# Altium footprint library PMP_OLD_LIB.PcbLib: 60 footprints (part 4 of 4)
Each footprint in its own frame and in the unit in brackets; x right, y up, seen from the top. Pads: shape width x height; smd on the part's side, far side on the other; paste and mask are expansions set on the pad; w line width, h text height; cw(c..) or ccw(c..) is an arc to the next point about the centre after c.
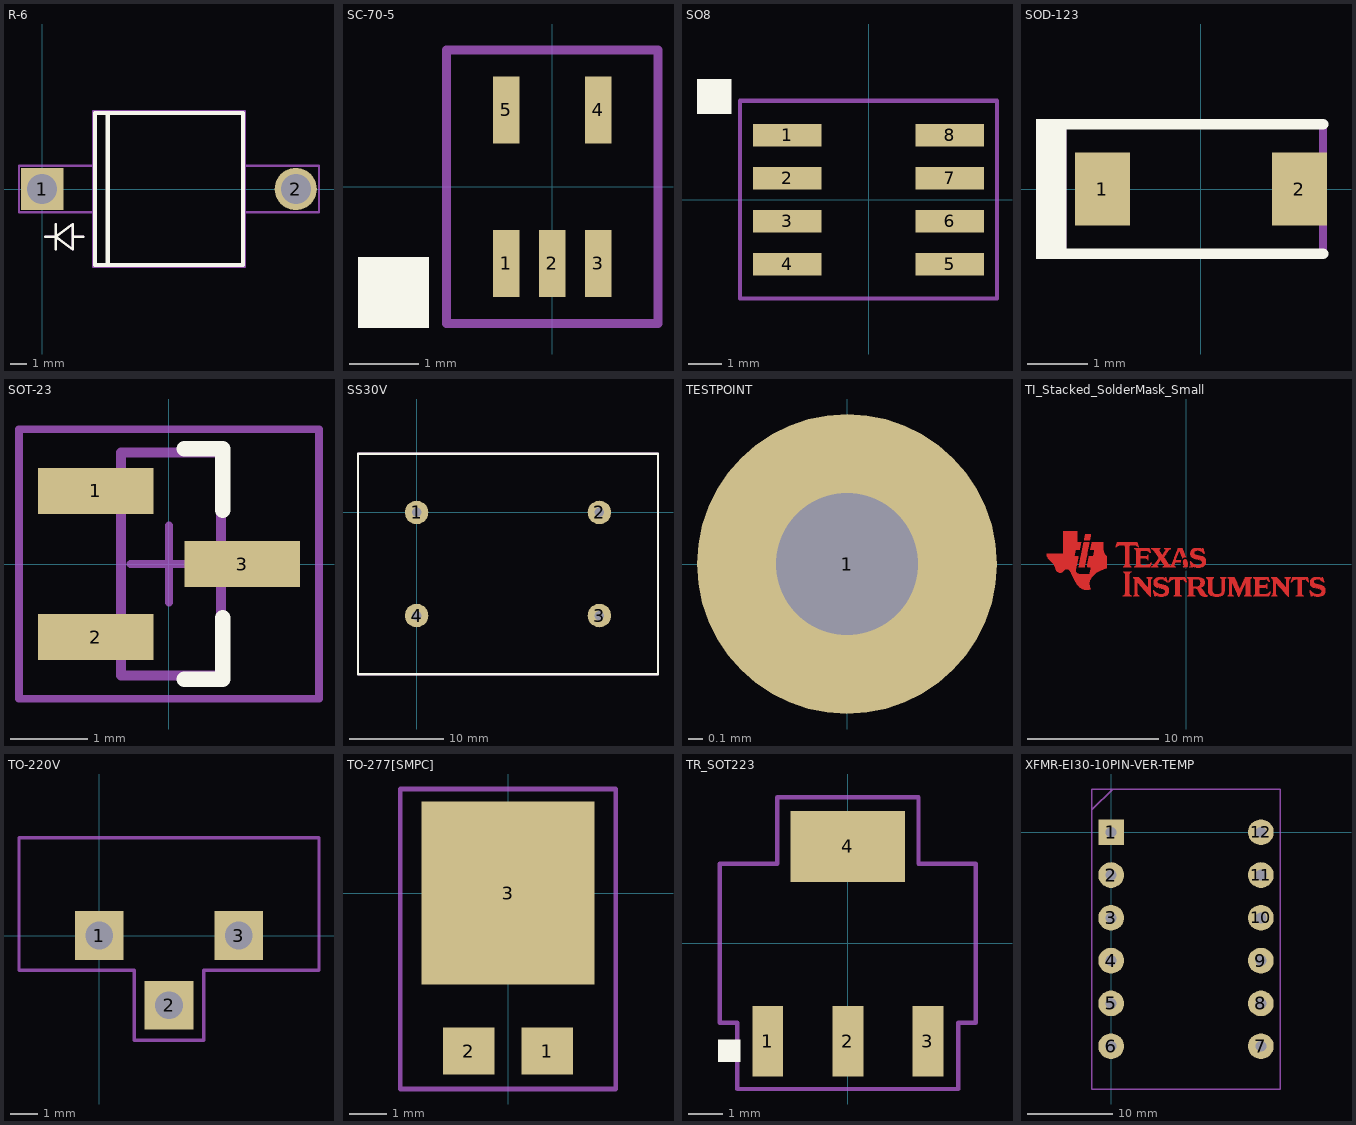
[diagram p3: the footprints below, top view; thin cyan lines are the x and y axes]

## R-6 [mil]
pads (2):
  rect 100x100 hole 71: 1(0,0)
  round 100 hole 71: 2(600,0)
Top Overlay:
  lines w6: 7.3,-113 32.3,-113 ; 32.3,-143 32.3,-83 ; 72.3,-113 97.3,-113 ; 32.3,-113 72.3,-143 72.3,-83 32.3,-113
  lines w10: 155,-180 155,180 ; 125,-180 475,-180 475,180 125,180 125,-180
Mechanical 5:
  lines w5: 7.3,-113 32.3,-113 ; 32.3,-143 32.3,-83 ; 72.3,-113 97.3,-113 ; 120,-55 -55,-55 -55,55 120,55 ; 480,-55 655,-55 655,55 480,55 ; 32.3,-113 72.3,-143 72.3,-83 32.3,-113 ; 120,-185 480,-185 480,185 120,185 120,-185
  text ".Designator" at 225,216.69 h60

## SC-70-5 [mil]
pads (5):
  rect 15x38 smd: 1(-25.9,-43.4) 2(0.1,-43.4) 3(26.1,-43.4) 4(26.1,43.6) 5(-25.9,43.6)
Top Overlay:
  region: -110,-80 -70,-80 -70,-40 -110,-40
Mechanical 5:
  lines w5: -59.9,-77.4 60.1,-77.4 60.1,77.6 -59.9,77.6 -59.9,-77.4
  text ".Designator" at -103,-12 h60
  text "*" at -50,-80 h25

## SO8 [mil]
pads (8):
  rect 80x26 smd: 1(-95,75) 2(-95,25) 3(-95,-25) 4(-95,-75) 5(94,-75) 6(94,-25) 7(94,25) 8(94,75)
Top Overlay:
  region: -160,100 -160,140 -200,140 -200,100
Mechanical 5:
  lines w5: -150,-115 149,-115 149,115 -150,115 -150,-115
  text ".Designator" at 40,155 h60

## SOD-123 [mm] "On Semi recommended land pattern"
height 1.35
pads (2):
  rect 0.915x1.22 smd: 1(-1.637,0) 2(1.637,0)
Top Overlay:
  rectangle: -2.743,-1.168 -2.235,1.168
  lines w0.178: -2.413,-1.079 2.032,-1.079 ; -2.413,1.079 2.032,1.079
Mechanical 5:
  rectangle: -2.743,-1.168 -2.235,1.168
  lines w0.127: -2.413,-1.079 2.032,-1.079 2.032,1.079 -2.413,1.079
  text ".Designator" at 1.143,2.819 h1.4
3D body: height 1.35, standoff 0, extent -1.932,-0.9 1.932,0.9

## SOT-23 [mm] "SOT23, 3-Leads, Body 2.9x1.3mm, Pitch 0.95mm, Lead Span 2.5mm, IPC Medium Density"
height 1.1
pads (3):
  rect 1.5x0.6 smd: 1(-0.95,0.95) 2(-0.95,-0.95) 3(0.95,0)
Top Overlay:
  lines w0.2: 0.2,-1.5 0.7,-1.5 0.7,-0.7 ; 0.2,1.5 0.7,1.5 0.7,0.7
Mechanical 5:
  lines w0.127: -1.16,-1.15 -1.16,-0.75 -0.625,-0.75 -0.625,0.75 -1.16,0.75 -1.16,1.15 -0.625,1.15 -0.625,1.45 0.675,1.45 0.675,0.2 1.21,0.2 1.21,-0.2 0.675,-0.2 0.675,-1.45 -0.625,-1.45 -0.625,-1.15 -1.16,-1.15
  text ".Designator" at -2.083,0.787 h1.52
Mechanical 15:
  lines w0.1: -0.5,0 0.5,0 ; 0,-0.5 0,0.5 ; -1.95,-1.75 1.95,-1.75 1.95,1.75 -1.95,1.75 -1.95,-1.75
3D body: height 1, standoff 0, extent -1.16,-1.45 1.21,1.45

## SS30V [mm]
pads (4):
  round 2.5 hole 1: 1(0,0) 2(19.5,0) 3(19.5,-11) 4(0,-11)
Top Overlay:
  lines w0.254: -6.25,-17.25 25.75,-17.25 25.75,6.25 -6.25,6.25 -6.25,-17.25
Mechanical 5:
  lines w0.254: -6.25,-17.25 -6.25,6.25 25.75,6.25 25.75,-17.25 -6.25,-17.25

## TESTPOINT [mil]
height 314.96
pads (1):
  round 80 hole 37.99: 1(0,0)

## TI_Stacked_SolderMask_Small [mil]
pads (1):
  rect 900x250 on Top Solder paste-125 mask-125: 0(0,0)
Top Layer:
  drawing of 18 lines, arcs and shapes, not listed

## TO-220V [mil]
pads (3):
  rect 70x70 hole 40: 1(0,0) 2(100,-100) 3(200,0)
Mechanical 5:
  lines w5: -115,-50 50,-50 50,-150 150,-150 150,-50 315,-50 315,140 -115,140 -115,-50
  text ".Designator" at -9.25,-88.9 h60

## TO-277[SMPC] [mil]
pads (3):
  rect 55x50 smd: 1(42,-168.6) 2(-42,-168.6)
  rect 185x195 smd: 3(0,0)
Mechanical 5:
  lines w5: -115,-209 115,-209 115,111 -115,111 -115,-209
  text ".Designator" at 165,-130 h60

## TR_SOT223 [mil]
pads (4):
  rect 35x80 smd: 1(-90.6,-110.9) 2(0,-110.9) 3(90.6,-110.9)
  rect 130x80 smd: 4(0,109.5)
Top Overlay:
  region: -146.8,-134.2 -146.8,-109.2 -121.8,-109.2 -121.8,-134.2
  region: -146.8,-134.2 -146.8,-109.2 -121.8,-109.2 -121.8,-134.2
Mechanical 5:
  lines w5: -145,-90 -125,-90 -125,-165 125,-165 125,-90 145,-90 145,90 80,90 80,165 -80,165 -80,90 -145,90 -145,-90
  text ".Designator" at 190,45 h60

## XFMR-EI30-10PIN-VER-TEMP [mm]
pads (12):
  rect 3x3 hole 1.27: 1(0,0)
  round 3 hole 1.27: 2(0,-5) 3(0,-10) 4(0,-15) 5(0,-20) 6(0,-25) 7(17.5,-25) 8(17.5,-20) 9(17.5,-15) 10(17.5,-10) 11(17.5,-5) 12(17.5,0)
Mechanical 5:
  lines w0.152: -2.175,2.675 0.2,5.05 ; -2.25,-30 19.75,-30 19.75,5 -2.25,5 -2.25,-30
